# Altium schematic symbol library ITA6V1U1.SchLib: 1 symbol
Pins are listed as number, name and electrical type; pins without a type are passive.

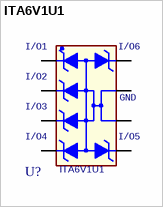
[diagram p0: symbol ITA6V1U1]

## ITA6V1U1
designator U?
footprint ST_SO8
pins: 1 I/O1, 2 I/O2, 3 I/O3, 4 I/O4, 5 I/O5, 6 GND, 7 GND1, 8 I/O6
